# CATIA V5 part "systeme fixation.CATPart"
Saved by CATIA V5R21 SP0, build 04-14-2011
Part number: FixationJustine
Bounding box of the stored display mesh (mm): x -25 to 25, y 0 to 68.95, z 0 to 3
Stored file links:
  C:\Users\2027.DESARCY-LEMIE30\Desktop\V14(17.02.2023)\systeme fixation.CATPart
  C:\Program Files\Dassault Systemes\B21\win_b64\reffiles\standard\MetricThickPitch.txt
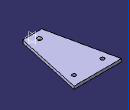
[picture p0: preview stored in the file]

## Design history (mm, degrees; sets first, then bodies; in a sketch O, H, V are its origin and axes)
Body1 (main body)
  Sketch1 on xy-plane, origin (0, 0, 0), H (1, 0, 0), V (0, 1, 0)
    construction line L1 (0, 81.499) -> (0, -38.501)
    point P1 (0, 81.499)
    line L2 (-25, 68.95) -> (25, 68.95)
    point P4 (25, 68.95)
    line L3 (25, 68.95) -> (10, 0)
    point P5 (10, 0)
    line L4 (10, 0) -> (-10, 0)
    point P6 (-10, 0)
    line L5 (-10, 0) -> (-25, 68.95)
    axis line L6 (-40, 58.95) -> (40, 58.95)
    length L2 = 50
    distance L1 P4 = 25
    length L4 = 20
    distance L1 P6 = 10
    distance L4 L2 = 68.95
    distance L6 L2 = 10
    coincidence: P1 V, P5 H
    vertical: L1 V
    horizontal: L2 H, L4 H, L6 H
  Pad1: profile Sketch1, direction (0, 0, 1), length 3
  Sketch2 on end face of Pad1, origin (-0.4128, 9.8194, 3), H (1, 0, 0), V (0, 1, 0)
    point P1 (0.4128, -2.3194)
    reference projected line E1 (-9.5872, -9.8194) -> (10.4128, -9.8194) from edge [face of Pad1 from Sketch1.L4 | end face of Pad1]
    reference projected point E2 (-9.5872, -9.8194) from vertex [face of Pad1 from Sketch1.L4 | end face of Pad1 | face of Pad1 from Sketch1.L5]
    distance P1 E1 = 7.5
    distance E2 P1 H = 10
  Hole1: placed by Sketch2, at (0, 7.5, 3) direction (0, 0, -1), diameter 4.917, through (limit type 6), threaded "M6", thread diameter 6, thread depth 3, pitch 1
  Sketch3 on end face of Pad1, origin (0, 0, 3), H (1, 0, 0), V (0, 1, 0)
    circle A1 centre (-15, 58.95) radius 2
    point P1 (-15, 58.95)
    reference projected line E1 (25, 68.95) -> (-25, 68.95) from edge [face of Pad1 from Sketch1.L2 | end face of Pad1]
    reference projected point E2 (-25, 68.95) from vertex [face of Pad1 from Sketch1.L2 | end face of Pad1 | face of Pad1 from Sketch1.L5]
    circle A2 centre (15, 58.95) radius 2
    point P2 (15, 58.95)
    reference projected line E3 (25, 68.95) -> (-25, 68.95) from edge [face of Pad1 from Sketch1.L2 | end face of Pad1]
    radius A1 = 2
    distance P1 E1 = 10
    distance P1 E2 H = 10
    radius A2 = 2
    distance P2 E3 = 10
    distance P1 P2 = 30
  Pocket1: profile Sketch3, direction (0, 0, -1), length 3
